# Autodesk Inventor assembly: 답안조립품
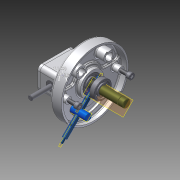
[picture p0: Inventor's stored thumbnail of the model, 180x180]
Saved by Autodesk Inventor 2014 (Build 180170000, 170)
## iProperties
Created: 2015-04
Part Number: 답안조립품
Document SubType Name: Assembly
Designer: basic
Author: basic
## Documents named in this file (15)
- C:\Users\basic\Desktop\350405V1006\답안조립품.iam
- C:\Users\basic\Desktop\350405V1006\본체.ipt
- C:\Users\basic\Desktop\350405V1006\M 5 x 12.ipt
- C:\Users\basic\Desktop\350405V1006\M 10 x 35.ipt
- C:\Users\basic\Desktop\350405V1006\멈춤링.ipt
- C:\Users\basic\Desktop\350405V1006\베어링62_22.ipt
- C:\Users\basic\Desktop\350405V1006\부시.ipt
- C:\Users\basic\Desktop\350405V1006\슬라이더.ipt
- C:\Users\basic\Desktop\350405V1006\슬라이더2.ipt
- C:\Users\basic\Desktop\350405V1006\슬라이더3.ipt
- C:\Users\basic\Desktop\350405V1006\축.ipt
- C:\Users\basic\Desktop\350405V1006\커버.ipt
- C:\Users\basic\Desktop\350405V1006\커버2.ipt
- C:\Users\basic\Desktop\350405V1006\평행핀.ipt
- C:\Users\basic\Desktop\350405V1006\가변스프링.ipt
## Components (6 placed, 4 different names)
1. M 5 x 12:1
2. M 10 x 35:1
3. KS B 1320 B B 5 x  20:1
4. 가변스프링:1
5. M 10 x 35:2
6. M 5 x 12:2
